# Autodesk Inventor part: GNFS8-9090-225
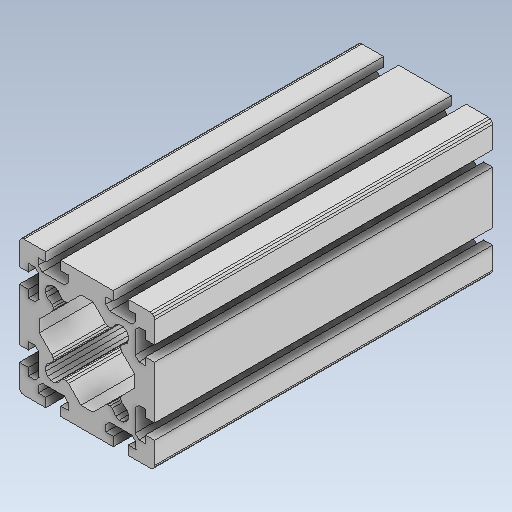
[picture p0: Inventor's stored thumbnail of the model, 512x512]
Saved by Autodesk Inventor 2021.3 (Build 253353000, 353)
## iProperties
Created: 2022-02
Part Number: GNFS8-9090-225
Material: 一般
Document SubType Name: Modeling
Designer: kengo
Density: 1 g/cm^3
Appearance: 既定
Author: kengo
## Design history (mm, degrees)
feature "GNFS8-9090-225"
node "ソリッド1"
